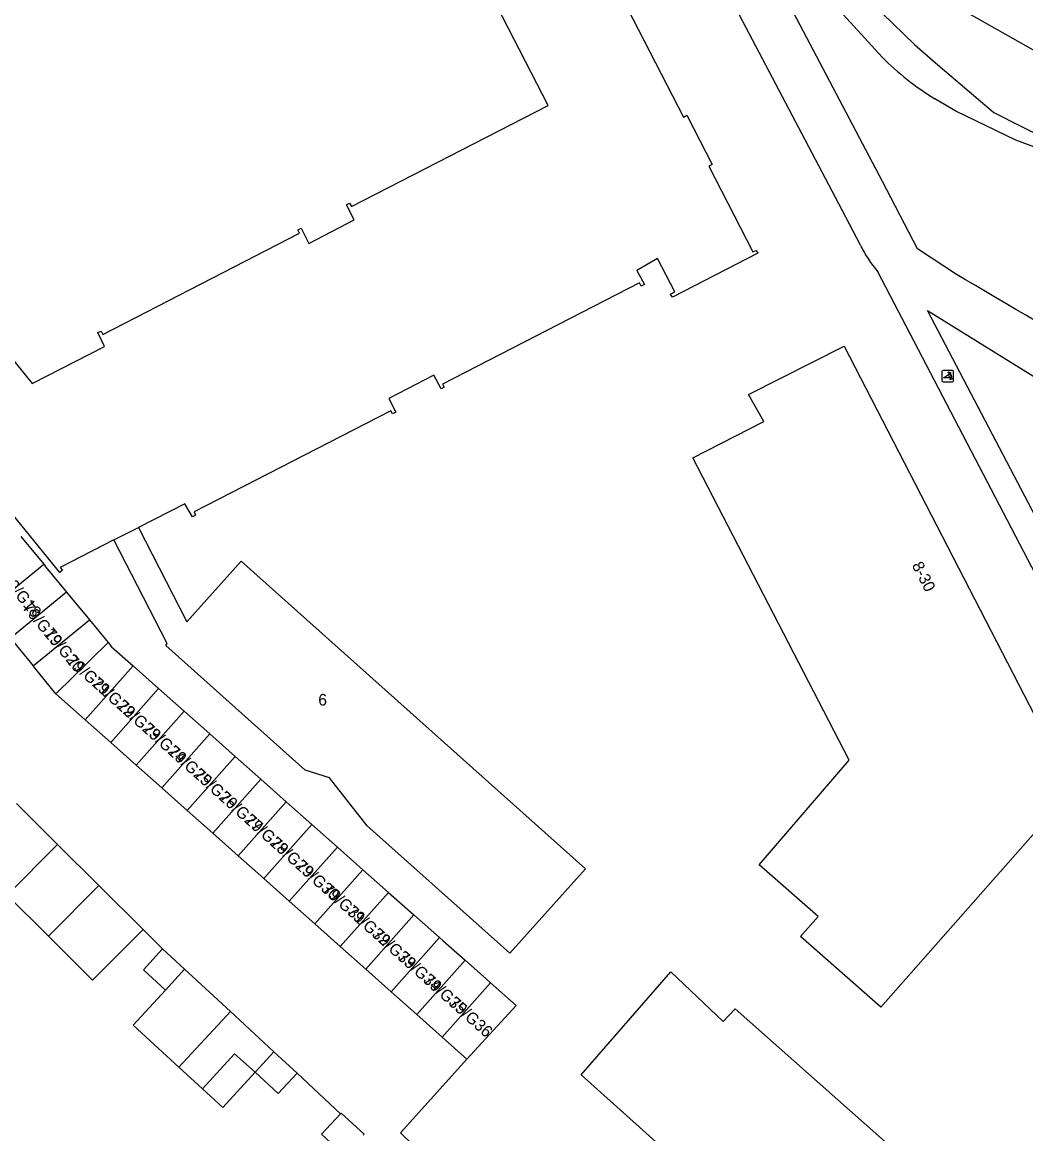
# Model space of a CAD drawing. Extents: x 162074 to 163034, y 381824 to 382557.
# Drawn here: x 162611.8 to 162697.9, y 382246.8 to 382342.2 of the extents above; entities that cross this region are included whole.
import ezdxf

# ---------------------------------------------------------------- set-up
doc = ezdxf.new("R2010")
doc.units = 0
for name, color, linetype in [('IMGEO_Meer_plas_ven_vijver', 7, 'Continuous'), ('IMGEO_Moeras', 7, 'Continuous'), ('IMGEO_Pand', 7, 'Continuous'), ('IMGEO_Pand_nummerreeks', 7, 'Continuous'), ('IMGEO_Poller', 7, 'Continuous'), ('IMGEO_Rijbaan_lokaal_open', 7, 'Continuous'), ('IMGEO_Voetpad_open', 7, 'Continuous')]:
    doc.layers.add(name, color=color, linetype=linetype)

msp = doc.modelspace()

# ---------------------------------------------------------------- linework, layer by layer
at = {"layer": 'IMGEO_Meer_plas_ven_vijver'}
for points in [[(162710.259, 382520.98), (162692.849, 382511.469), (162629.58, 382474.951), (162626.098, 382472.488), (162622.191, 382467.817), (162621.002, 382465.184), (162620.578, 382463.316), (162621.045, 382460.428), (162622.828, 382456.734), (162655.864, 382391.638), (162656.393, 382390.427), (162656.51, 382390.159), (162659.554, 382383.192), (162659.687, 382382.888), (162664.91, 382374.037), (162668.534, 382366.61), (162675.049, 382356.003), (162678.84, 382351), (162682.877, 382345.671), (162688.382, 382340.317), (162690.182, 382338.739), (162695.197, 382334.461), (162704.456, 382329.771)], [(162698.796, 382339.719), (162691.097, 382344.051), (162684.773, 382349.794), (162681.726, 382352.965), (162681.239, 382353.472), (162677.768, 382358.009), (162673.895, 382365.438), (162668.813, 382375.186), (162665.533, 382380.666), (162664.028, 382385.561), (162663.92, 382385.776), (162660.708, 382392.175), (162660.59, 382392.409), (162659.516, 382393.677), (162631.576, 382448.284), (162625.758, 382460.004), (162625.503, 382461.108), (162625.928, 382462.764), (162627.159, 382463.783), (162630.047, 382465.439), (162709.622, 382508.963)]]:
    msp.add_lwpolyline(points, dxfattribs=at)
at = {"layer": 'IMGEO_Moeras'}
for points in [[(162685.594, 382339.219), (162679.829, 382345.587), (162677.096, 382349.813), (162675.897, 382351.667), (162663.408, 382373.609), (162659.069, 382380.935)], [(162706.062, 382328.779), (162697.065, 382332.099), (162691.917, 382334.586), (162690.114, 382335.645)]]:
    msp.add_lwpolyline(points, dxfattribs=at)
msp.add_arc((162704.626, 382358.644), 27.195, 225.58467, 237.74793, dxfattribs=at)
at = {"layer": 'IMGEO_Pand'}
for points in [[(162611.12, 382350.618), (162589.586, 382339.533), (162611.465, 382312.682), (162612.672, 382311.203), (162618.877, 382314.387), (162618.292, 382315.57), (162618.572, 382315.709), (162618.724, 382315.426), (162635.597, 382324.114), (162635.454, 382324.411), (162635.738, 382324.547), (162636.392, 382323.239), (162640.303, 382325.251), (162639.622, 382326.553), (162639.903, 382326.699), (162640.063, 382326.407), (162656.94, 382335.079), (162652.535, 382343.629)], [(162619.67, 382297.77), (162615.06, 382295.417), (162615.255, 382295.181), (162615.02, 382294.984), (162582.066, 382335.498), (162581.116, 382337.326), (162580.228, 382336.865), (162579.215, 382338.818), (162575.86, 382337.077), (162569.135, 382350.036)], [(162660.381, 382349.989), (162668.563, 382334.081), (162668.835, 382334.241), (162671.015, 382330.01), (162670.73, 382329.864), (162674.514, 382322.517), (162674.796, 382322.637), (162674.928, 382322.386), (162667.598, 382318.618), (162667.45, 382318.887), (162667.8, 382319.08), (162666.333, 382321.949), (162664.55, 382320.904), (162665.207, 382319.702), (162664.926, 382319.568), (162664.79, 382319.834), (162647.881, 382311.153), (162648.029, 382310.883), (162647.745, 382310.741), (162647.137, 382311.922), (162643.274, 382309.913), (162643.861, 382308.736), (162643.581, 382308.59), (162643.443, 382308.857), (162626.551, 382300.181), (162626.686, 382299.908), (162626.42, 382299.755), (162625.772, 382300.883), (162621.786, 382298.849)], [(162675.458, 382307.938), (162674.145, 382310.265), (162682.332, 382314.424), (162701.957, 382276.331), (162685.483, 382257.651), (162678.597, 382263.71), (162680.105, 382265.424), (162675.055, 382269.868), (162682.765, 382278.87), (162669.362, 382304.812), (162675.458, 382307.938)], [(162621.786, 382298.849), (162625.935, 382290.728), (162630.583, 382295.936), (162660.135, 382269.528), (162653.642, 382262.29), (162641.421, 382273.237), (162638.174, 382277.345), (162636.073, 382277.989), (162624.124, 382288.707), (162624.255, 382288.893), (162619.67, 382297.77)], [(162619.67, 382297.77), (162621.786, 382298.849)], [(162611.699, 382298.065), (162613.653, 382295.678)], [(162608.833, 382291.728), (162613.653, 382295.678)], [(162613.653, 382295.678), (162613.845, 382295.443), (162615.612, 382293.293)], [(162615.612, 382293.293), (162610.789, 382289.341)], [(162615.612, 382293.293), (162617.571, 382290.909)], [(162612.745, 382286.955), (162617.571, 382290.909)], [(162617.571, 382290.909), (162619.177, 382288.954)], [(162610.789, 382289.341), (162612.745, 382286.955)], [(162619.177, 382288.954), (162614.701, 382284.568)], [(162619.177, 382288.954), (162619.477, 382288.589), (162621.32, 382286.954)], [(162614.701, 382284.568), (162612.745, 382286.955)], [(162621.32, 382286.954), (162617.21, 382282.335)], [(162621.32, 382286.954), (162623.511, 382285.01)], [(162614.701, 382284.568), (162617.21, 382282.335)], [(162619.398, 382280.388), (162623.511, 382285.01)], [(162623.511, 382285.01), (162625.702, 382283.066)], [(162625.702, 382283.066), (162621.587, 382278.441)], [(162625.702, 382283.066), (162627.894, 382281.122)], [(162617.21, 382282.335), (162619.398, 382280.388)], [(162623.775, 382276.493), (162627.894, 382281.122)], [(162627.894, 382281.122), (162630.085, 382279.178)], [(162619.398, 382280.388), (162621.587, 382278.441)], [(162630.085, 382279.178), (162625.964, 382274.546)], [(162630.085, 382279.178), (162632.276, 382277.234)], [(162621.587, 382278.441), (162623.775, 382276.493)], [(162632.276, 382277.234), (162628.152, 382272.599)], [(162632.276, 382277.234), (162634.467, 382275.29)], [(162625.964, 382274.546), (162623.775, 382276.493)], [(162614.839, 382271.629), (162611.321, 382275.129)], [(162630.34, 382270.652), (162634.467, 382275.29)], [(162634.467, 382275.29), (162636.659, 382273.346)], [(162625.964, 382274.546), (162628.152, 382272.599)], [(162632.529, 382268.704), (162636.659, 382273.346)], [(162636.659, 382273.346), (162638.85, 382271.401)], [(162628.152, 382272.599), (162630.34, 382270.652)], [(162614.839, 382271.629), (162610.5, 382267.267)], [(162618.386, 382268.101), (162614.839, 382271.629)], [(162638.85, 382271.401), (162634.717, 382266.757)], [(162638.85, 382271.401), (162641.041, 382269.457)], [(162630.34, 382270.652), (162632.529, 382268.704)], [(162636.905, 382264.81), (162641.041, 382269.457)], [(162641.041, 382269.457), (162643.232, 382267.513)], [(162634.717, 382266.757), (162632.529, 382268.704)], [(162614.046, 382263.739), (162618.386, 382268.101)], [(162622.186, 382264.321), (162618.386, 382268.101)], [(162639.094, 382262.862), (162643.232, 382267.513)], [(162643.232, 382267.513), (162645.424, 382265.569)], [(162614.046, 382263.739), (162610.5, 382267.267)], [(162634.717, 382266.757), (162636.905, 382264.81)], [(162645.424, 382265.569), (162641.282, 382260.915)], [(162645.424, 382265.569), (162647.615, 382263.625)], [(162636.905, 382264.81), (162639.094, 382262.862)], [(162622.186, 382264.321), (162617.846, 382259.958), (162614.046, 382263.739)], [(162647.615, 382263.625), (162643.471, 382258.968)], [(162647.615, 382263.625), (162647.906, 382263.367), (162649.81, 382261.686)], [(162624.095, 382259.118), (162622.201, 382260.866), (162623.848, 382262.651)], [(162625.742, 382260.903), (162623.848, 382262.651)], [(162641.282, 382260.915), (162639.094, 382262.862)], [(162645.659, 382257.02), (162649.81, 382261.686)], [(162649.81, 382261.686), (162651.649, 382260.063), (162652.007, 382259.747)], [(162624.095, 382259.118), (162625.742, 382260.903)], [(162629.668, 382257.278), (162625.742, 382260.903)], [(162641.282, 382260.915), (162643.471, 382258.968)], [(162667.476, 382260.684), (162671.97, 382256.431), (162672.98, 382257.513), (162691.621, 382240.981), (162709.224, 382249.82), (162713.342, 382241.757), (162712.156, 382241.132), (162714.087, 382237.279), (162689.826, 382224.866), (162659.772, 382251.85), (162667.476, 382260.684)], [(162652.007, 382259.747), (162647.847, 382255.073)], [(162652.007, 382259.747), (162654.203, 382257.809), (162649.967, 382253.187)], [(162625.256, 382252.498), (162623.126, 382254.457), (162621.329, 382256.11), (162624.095, 382259.118)], [(162643.471, 382258.968), (162645.659, 382257.02)], [(162629.668, 382257.278), (162625.256, 382252.498)], [(162633.408, 382253.826), (162629.668, 382257.278)], [(162647.847, 382255.073), (162645.659, 382257.02)], [(162647.847, 382255.073), (162649.967, 382253.187)], [(162631.795, 382252.079), (162630.015, 382253.645), (162627.264, 382250.652)], [(162631.795, 382252.079), (162633.408, 382253.826)], [(162635.389, 382251.998), (162633.408, 382253.826)], [(162627.264, 382250.652), (162625.256, 382252.498)], [(162631.795, 382252.079), (162629.008, 382249.048), (162627.264, 382250.652)], [(162635.389, 382251.998), (162633.776, 382250.25), (162631.795, 382252.079)], [(162639.459, 382244.927), (162637.5, 382246.735), (162639.115, 382248.484)], [(162641.061, 382246.663), (162641.147, 382246.756), (162639.188, 382248.564), (162639.115, 382248.484)]]:
    msp.add_lwpolyline(points, dxfattribs=at)
at = {"layer": 'IMGEO_Poller'}
for p, q in [((162690.737, 382312.237), (162690.737, 382311.43)), ((162690.737, 382312.237), (162690.737, 382311.43)), ((162691.639, 382312.332), (162690.831, 382312.332)), ((162691.639, 382312.332), (162690.831, 382312.332)), ((162691.733, 382311.43), (162691.733, 382312.237)), ((162691.733, 382311.43), (162691.733, 382312.237)), ((162690.831, 382311.335), (162691.639, 382311.335)), ((162690.831, 382311.335), (162691.639, 382311.335))]:
    msp.add_line(p, q, dxfattribs=at)
for points in [[(162691.372, 382311.688), (162690.859, 382311.688), (162691.289, 382311.963)], [(162691.416, 382312.061), (162691.404, 382311.988), (162691.279, 382312.193)], [(162691.279, 382312.193), (162691.51, 382312.127), (162691.439, 382312.095)], [(162691.432, 382311.516), (162691.498, 382311.747), (162691.528, 382311.679)], [(162691.564, 382311.652), (162691.636, 382311.641), (162691.432, 382311.516)]]:
    msp.add_lwpolyline(points, dxfattribs=at)
for centre, radius, start, end in [((162690.831, 382312.237), 0.0946, 90, 180), ((162690.831, 382312.237), 0.0946, 90, 180), ((162691.639, 382312.237), 0.0946, 0, 90), ((162691.639, 382312.237), 0.0946, 0, 90), ((162690.831, 382311.43), 0.0946, 180, 270), ((162690.831, 382311.43), 0.0946, 180, 270), ((162691.044, 382311.738), 0.332, 351.32473, 42.4854), ((162691.058, 382311.748), 0.476, 351.75274, 41.16905), ((162691.058, 382311.748), 0.516, 349.35686, 42.29123), ((162691.639, 382311.43), 0.0946, 270, 0), ((162691.639, 382311.43), 0.0946, 270, 0)]:
    msp.add_arc(centre, radius, start, end, dxfattribs=at)
at = {"layer": 'IMGEO_Rijbaan_lokaal_open'}
for points in [[(162683.739, 382323.087), (162682.16, 382326.102), (162681.886, 382326.625), (162667.343, 382354.291), (162653.489, 382381.075)], [(162691.887, 382320.619), (162688.631, 382322.776), (162685.647, 382328.543), (162659.054, 382379.075), (162658.899, 382380.293)], [(162716.544, 382260.482), (162710.988, 382271.384), (162685.248, 382320.783)], [(162689.498, 382317.469), (162716.516, 382300.701)], [(162718.626, 382261.641), (162718.413, 382262.206), (162721.565, 382263.65), (162719.216, 382268.778), (162715.898, 382267.027), (162713.326, 382271.991), (162689.498, 382317.469)]]:
    msp.add_lwpolyline(points, dxfattribs=at)
for centre, radius, start, end in [((162694.039, 382328.187), 11.494, 206.34136, 220.10406), ((162345.045, 381724.902), 689.332, 57.125173, 59.790915)]:
    msp.add_arc(centre, radius, start, end, dxfattribs=at)
at = {"layer": 'IMGEO_Voetpad_open'}
for points in [[(162623.848, 382262.651), (162622.186, 382264.321)], [(162649.967, 382253.187), (162644.258, 382246.855), (162646.441, 382244.752), (162644.984, 382243.098)], [(162639.115, 382248.484), (162635.389, 382251.998)]]:
    msp.add_lwpolyline(points, dxfattribs=at)

# ---------------------------------------------------------------- texts
at = {"layer": 'IMGEO_Pand_nummerreeks'}
for s, rotation, p in [('8-30', 296.92771, (162688.13, 382295.601)), ('79/G18', 309.38242, (162609.98, 382294.408)), ('79/G19', 309.38242, (162611.763, 382291.932)), ('79/G20', 309.38242, (162613.644, 382289.714)), ('79/G21', 318.1656, (162615.574, 382287.243)), ('79/G22', 318.1656, (162617.678, 382285.36)), ('6', 0, (162637.216, 382283.549)), ('79/G23', 318.1656, (162619.872, 382283.396)), ('79/G24', 318.1656, (162622.062, 382281.435)), ('79/G25', 318.1656, (162624.252, 382279.475)), ('79/G26', 318.1656, (162626.442, 382277.514)), ('79/G27', 318.1656, (162628.632, 382275.554)), ('79/G28', 318.1656, (162630.824, 382273.591)), ('79/G29', 318.1656, (162633.01, 382271.635)), ('79/G30', 318.1656, (162635.204, 382269.67)), ('79/G31', 318.1656, (162637.474, 382267.639)), ('79/G32', 318.1656, (162639.577, 382265.756)), ('79/G33', 318.1656, (162641.772, 382263.791)), ('79/G34', 318.1656, (162643.962, 382261.831)), ('79/G35', 318.1656, (162646.152, 382259.87)), ('79/G36', 318.1656, (162648.342, 382257.91))]:
    msp.add_text(s, height=1, rotation=rotation, dxfattribs=at).set_placement(p)

doc.saveas('drawing.dxf')
